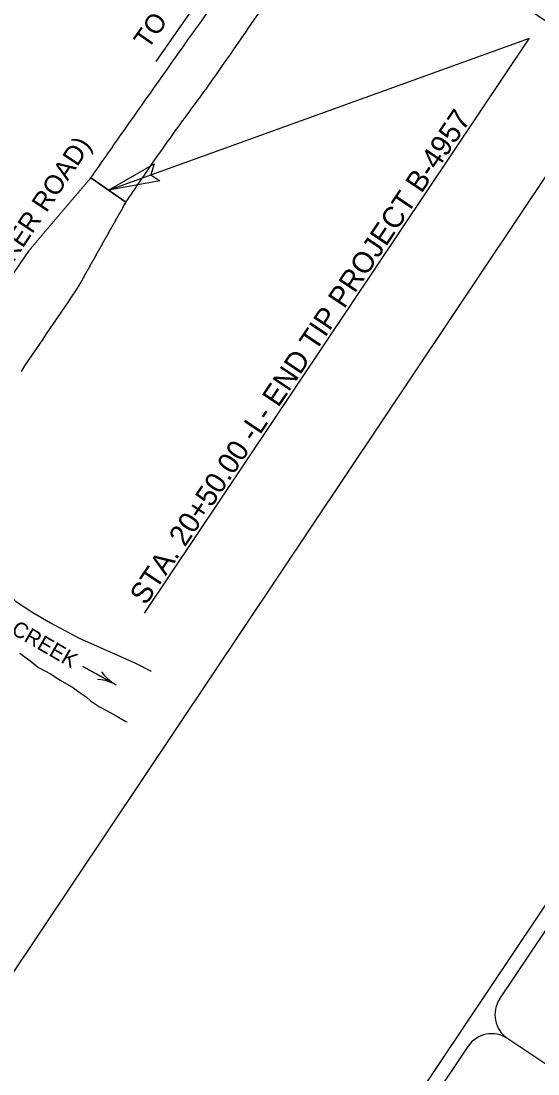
# Model space of a CAD drawing. Extents: x 1715610 to 1720914, y 798298 to 802505.
# Drawn here: x 1717668 to 1717939, y 800836 to 801387 of the extents above; entities that cross this region are included whole.
import ezdxf

# ---------------------------------------------------------------- set-up
doc = ezdxf.new("R2010")
doc.units = 0
for name, color, linetype in [('Default', 7, 'Continuous'), ('Old_Level_3', 7, 'Continuous'), ('Prop DSN Text', 7, 'Continuous'), ('Prop Paved Shoulder', 7, 'Continuous'), ('Prop Shade Medium', 7, 'Continuous'), ('Prop Terminator CELL', 7, 'Continuous'), ('Sheet Title CELL', 7, 'Continuous')]:
    doc.layers.add(name, color=color, linetype=linetype)

# ---------------------------------------------------------------- blocks, each defined once
blk = doc.blocks.new('EXIST HYDRO RIVER FLOW ARROW')
at = {"layer": 'Default'}
blk.add_line((0, 0), (0, 0), dxfattribs=at)
blk.add_lwpolyline([(0, 0.04575), (0.03775, 0.03), (0.07725, 0.01725), (0.118, 0.00775), (0.159, 0.0015), (0.2, 0), (-0.2, 0), (0.2, 0), (0.159, -0.0015), (0.118, -0.00775), (0.07725, -0.01725), (0.03775, -0.03), (0, -0.04575)], dxfattribs=at)

msp = doc.modelspace()

# ---------------------------------------------------------------- linework, layer by layer
at = {"layer": 'Old_Level_3'}
for points in [[(1717605.94, 801111.76), (1717612.79, 801109.04), (1717616.17, 801107.46), (1717622.88, 801104.61), (1717634.87, 801098.17), (1717639.69, 801095.36), (1717644.84, 801093.04), (1717654.93, 801089.79), (1717659.08, 801087.53), (1717662.76, 801085.55), (1717665.17, 801083.21), (1717674.36, 801077.27), (1717683.55, 801072), (1717698.55, 801063.91), (1717727.72, 801050.92)], [(1717667.51, 801055.97), (1717672.17, 801052.48), (1717677.33, 801048.47), (1717683.5, 801045.15), (1717688.67, 801041.86), (1717695.56, 801037.89), (1717698.56, 801035.68), (1717702.27, 801033.19), (1717704.51, 801031.03), (1717709.23, 801027.9), (1717712.43, 801026.24), (1717717.13, 801023.81), (1717723.03, 801020.3), (1717723.71, 801020.05)], [(1717727.61, 801050.97), (1717727.72, 801050.92), (1717736.2, 801046.69)]]:
    msp.add_lwpolyline(points, dxfattribs=at)
for points in [[(1717704.66, 801304.87), (1717720.57, 801327.61), (1717755.53, 801377.08), (1717788.31, 801423.35), (1717810.22, 801454.82)], [(1717723, 801292.11), (1717738.53, 801314.79), (1717747.21, 801327.08), (1717756.08, 801339.25), (1717764.97, 801351.4), (1717773.68, 801363.68), (1717805.81, 801410.44), (1717827.75, 801442.62)]]:
    msp.add_spline(points, degree=3, dxfattribs=at)
at = {"layer": 'Prop DSN Text'}
for p, q in [((1717738.85, 801365.79), (1717793.38, 801444.08)), ((1717713.83, 801298.49), (1717934.3, 801377.96)), ((1717732.84, 801076.97), (1717934.3, 801377.96))]:
    msp.add_line(p, q, dxfattribs=at)
msp.add_lwpolyline([(1717114.49, 800787.07), (1717648.17, 801584.42), (1717980.46, 801362.01), (1717446.79, 800564.66)], close=True, dxfattribs=at)
at = {"layer": 'Prop Paved Shoulder'}
msp.add_line((1717723, 801292.11), (1717704.66, 801304.87), dxfattribs=at)
for radius in [5716, 5684]:
    msp.add_arc((1722391.71, 798042.03), radius, 145.65923, 146.20506, dxfattribs=at)
for points in [[(1717672.02, 801266.5), (1717672.46, 801267.02), (1717672.9, 801267.54), (1717673.34, 801268.06), (1717673.78, 801268.58), (1717674.22, 801269.1), (1717674.66, 801269.62), (1717675.1, 801270.14), (1717675.54, 801270.66), (1717675.98, 801271.18), (1717676.41, 801271.7), (1717676.85, 801272.22), (1717677.29, 801272.74), (1717677.73, 801273.26), (1717678.17, 801273.78), (1717678.61, 801274.3), (1717679.05, 801274.82), (1717679.49, 801275.34), (1717679.93, 801275.86), (1717680.37, 801276.38), (1717680.81, 801276.9), (1717681.25, 801277.42), (1717681.69, 801277.94), (1717682.13, 801278.46), (1717682.57, 801278.98), (1717683.01, 801279.5), (1717683.45, 801280.02), (1717683.9, 801280.54), (1717684.34, 801281.06), (1717684.78, 801281.58), (1717685.22, 801282.1), (1717685.66, 801282.61), (1717686.1, 801283.13), (1717686.54, 801283.65), (1717686.98, 801284.17), (1717687.42, 801284.69), (1717687.86, 801285.21), (1717688.3, 801285.73), (1717688.74, 801286.24), (1717689.19, 801286.76), (1717689.63, 801287.28), (1717690.07, 801287.8), (1717690.51, 801288.32), (1717690.95, 801288.84), (1717691.39, 801289.35), (1717691.83, 801289.87), (1717692.27, 801290.39), (1717692.72, 801290.91), (1717693.16, 801291.43), (1717693.6, 801291.94), (1717694.04, 801292.46), (1717694.48, 801292.98), (1717694.93, 801293.5), (1717695.37, 801294.02), (1717695.81, 801294.53), (1717696.25, 801295.05), (1717696.69, 801295.57), (1717697.14, 801296.09), (1717697.58, 801296.6), (1717698.02, 801297.12), (1717698.46, 801297.64), (1717698.91, 801298.15), (1717699.35, 801298.67), (1717699.79, 801299.19), (1717700.23, 801299.71), (1717700.68, 801300.22), (1717701.12, 801300.74), (1717701.56, 801301.26), (1717702, 801301.77), (1717702.45, 801302.29), (1717702.89, 801302.81), (1717703.33, 801303.32), (1717703.78, 801303.84), (1717704.66, 801304.87)], [(1717698.44, 801248.45), (1717698.77, 801249.04), (1717699.1, 801249.63), (1717699.43, 801250.22), (1717699.76, 801250.81), (1717700.09, 801251.4), (1717700.42, 801252), (1717700.75, 801252.59), (1717701.08, 801253.18), (1717701.41, 801253.77), (1717701.74, 801254.36), (1717702.07, 801254.95), (1717702.4, 801255.54), (1717702.73, 801256.13), (1717703.06, 801256.72), (1717703.39, 801257.31), (1717703.72, 801257.9), (1717704.05, 801258.49), (1717704.38, 801259.09), (1717704.71, 801259.68), (1717705.04, 801260.27), (1717705.37, 801260.86), (1717705.7, 801261.45), (1717706.03, 801262.04), (1717706.36, 801262.63), (1717706.69, 801263.22), (1717707.03, 801263.81), (1717707.36, 801264.4), (1717707.69, 801264.99), (1717708.02, 801265.58), (1717708.35, 801266.17), (1717708.68, 801266.76), (1717709.01, 801267.35), (1717709.34, 801267.94), (1717709.68, 801268.53), (1717710.01, 801269.12), (1717710.34, 801269.71), (1717710.67, 801270.3), (1717711, 801270.89), (1717711.33, 801271.48), (1717711.67, 801272.07), (1717712, 801272.66), (1717712.33, 801273.25), (1717712.66, 801273.84), (1717712.99, 801274.43), (1717713.33, 801275.02), (1717713.66, 801275.61), (1717713.99, 801276.2), (1717714.32, 801276.79), (1717714.66, 801277.38), (1717714.99, 801277.97), (1717715.32, 801278.56), (1717715.66, 801279.15), (1717715.99, 801279.74), (1717716.32, 801280.33), (1717716.65, 801280.92), (1717716.99, 801281.5), (1717717.32, 801282.09), (1717717.65, 801282.68), (1717717.99, 801283.27), (1717718.32, 801283.86), (1717718.65, 801284.45), (1717718.99, 801285.04), (1717719.32, 801285.63), (1717719.66, 801286.22), (1717719.99, 801286.81), (1717720.32, 801287.4), (1717720.66, 801287.99), (1717720.99, 801288.57), (1717721.33, 801289.16), (1717721.66, 801289.75), (1717721.99, 801290.34), (1717722.33, 801290.93), (1717723, 801292.11)]]:
    msp.add_spline(points, degree=3, dxfattribs=at)
at = {"layer": 'Prop Shade Medium'}
msp.add_line((1717704.66, 801304.87), (1717723, 801292.11), dxfattribs=at)
msp.add_line((1717704.66, 801304.87), (1717723, 801292.11), dxfattribs=at)
msp.add_arc((1722391.71, 798042.03), 5684, 145.65923, 146.20506, dxfattribs=at)
msp.add_arc((1722391.71, 798042.03), 5684, 145.65923, 146.20506, dxfattribs=at)
for points in [[(1717672.02, 801266.5), (1717672.46, 801267.02), (1717672.9, 801267.54), (1717673.34, 801268.06), (1717673.78, 801268.58), (1717674.22, 801269.1), (1717674.66, 801269.62), (1717675.1, 801270.14), (1717675.54, 801270.66), (1717675.98, 801271.18), (1717676.41, 801271.7), (1717676.85, 801272.22), (1717677.29, 801272.74), (1717677.73, 801273.26), (1717678.17, 801273.78), (1717678.61, 801274.3), (1717679.05, 801274.82), (1717679.49, 801275.34), (1717679.93, 801275.86), (1717680.37, 801276.38), (1717680.81, 801276.9), (1717681.25, 801277.42), (1717681.69, 801277.94), (1717682.13, 801278.46), (1717682.57, 801278.98), (1717683.01, 801279.5), (1717683.45, 801280.02), (1717683.9, 801280.54), (1717684.34, 801281.06), (1717684.78, 801281.58), (1717685.22, 801282.1), (1717685.66, 801282.61), (1717686.1, 801283.13), (1717686.54, 801283.65), (1717686.98, 801284.17), (1717687.42, 801284.69), (1717687.86, 801285.21), (1717688.3, 801285.73), (1717688.74, 801286.24), (1717689.19, 801286.76), (1717689.63, 801287.28), (1717690.07, 801287.8), (1717690.51, 801288.32), (1717690.95, 801288.84), (1717691.39, 801289.35), (1717691.83, 801289.87), (1717692.27, 801290.39), (1717692.72, 801290.91), (1717693.16, 801291.43), (1717693.6, 801291.94), (1717694.04, 801292.46), (1717694.48, 801292.98), (1717694.93, 801293.5), (1717695.37, 801294.02), (1717695.81, 801294.53), (1717696.25, 801295.05), (1717696.69, 801295.57), (1717697.14, 801296.09), (1717697.58, 801296.6), (1717698.02, 801297.12), (1717698.46, 801297.64), (1717698.91, 801298.15), (1717699.35, 801298.67), (1717699.79, 801299.19), (1717700.23, 801299.71), (1717700.68, 801300.22), (1717701.12, 801300.74), (1717701.56, 801301.26), (1717702, 801301.77), (1717702.45, 801302.29), (1717702.89, 801302.81), (1717703.33, 801303.32), (1717703.78, 801303.84), (1717704.66, 801304.87)], [(1717672.02, 801266.5), (1717672.46, 801267.02), (1717672.9, 801267.54), (1717673.34, 801268.06), (1717673.78, 801268.58), (1717674.22, 801269.1), (1717674.66, 801269.62), (1717675.1, 801270.14), (1717675.54, 801270.66), (1717675.98, 801271.18), (1717676.41, 801271.7), (1717676.85, 801272.22), (1717677.29, 801272.74), (1717677.73, 801273.26), (1717678.17, 801273.78), (1717678.61, 801274.3), (1717679.05, 801274.82), (1717679.49, 801275.34), (1717679.93, 801275.86), (1717680.37, 801276.38), (1717680.81, 801276.9), (1717681.25, 801277.42), (1717681.69, 801277.94), (1717682.13, 801278.46), (1717682.57, 801278.98), (1717683.01, 801279.5), (1717683.45, 801280.02), (1717683.9, 801280.54), (1717684.34, 801281.06), (1717684.78, 801281.58), (1717685.22, 801282.1), (1717685.66, 801282.61), (1717686.1, 801283.13), (1717686.54, 801283.65), (1717686.98, 801284.17), (1717687.42, 801284.69), (1717687.86, 801285.21), (1717688.3, 801285.73), (1717688.74, 801286.24), (1717689.19, 801286.76), (1717689.63, 801287.28), (1717690.07, 801287.8), (1717690.51, 801288.32), (1717690.95, 801288.84), (1717691.39, 801289.35), (1717691.83, 801289.87), (1717692.27, 801290.39), (1717692.72, 801290.91), (1717693.16, 801291.43), (1717693.6, 801291.94), (1717694.04, 801292.46), (1717694.48, 801292.98), (1717694.93, 801293.5), (1717695.37, 801294.02), (1717695.81, 801294.53), (1717696.25, 801295.05), (1717696.69, 801295.57), (1717697.14, 801296.09), (1717697.58, 801296.6), (1717698.02, 801297.12), (1717698.46, 801297.64), (1717698.91, 801298.15), (1717699.35, 801298.67), (1717699.79, 801299.19), (1717700.23, 801299.71), (1717700.68, 801300.22), (1717701.12, 801300.74), (1717701.56, 801301.26), (1717702, 801301.77), (1717702.45, 801302.29), (1717702.89, 801302.81), (1717703.33, 801303.32), (1717703.78, 801303.84), (1717704.66, 801304.87)], [(1717723, 801292.11), (1717722.33, 801290.93), (1717721.99, 801290.34), (1717721.66, 801289.75), (1717721.33, 801289.16), (1717720.99, 801288.57), (1717720.66, 801287.99), (1717720.32, 801287.4), (1717719.99, 801286.81), (1717719.66, 801286.22), (1717719.32, 801285.63), (1717718.99, 801285.04), (1717718.65, 801284.45), (1717718.32, 801283.86), (1717717.99, 801283.27), (1717717.65, 801282.68), (1717717.32, 801282.09), (1717716.99, 801281.5), (1717716.65, 801280.92), (1717716.32, 801280.33), (1717715.99, 801279.74), (1717715.66, 801279.15), (1717715.32, 801278.56), (1717714.99, 801277.97), (1717714.66, 801277.38), (1717714.32, 801276.79), (1717713.99, 801276.2), (1717713.66, 801275.61), (1717713.33, 801275.02), (1717712.99, 801274.43), (1717712.66, 801273.84), (1717712.33, 801273.25), (1717712, 801272.66), (1717711.67, 801272.07), (1717711.33, 801271.48), (1717711, 801270.89), (1717710.67, 801270.3), (1717710.34, 801269.71), (1717710.01, 801269.12), (1717709.68, 801268.53), (1717709.34, 801267.94), (1717709.01, 801267.35), (1717708.68, 801266.76), (1717708.35, 801266.17), (1717708.02, 801265.58), (1717707.69, 801264.99), (1717707.36, 801264.4), (1717707.03, 801263.81), (1717706.69, 801263.22), (1717706.36, 801262.63), (1717706.03, 801262.04), (1717705.7, 801261.45), (1717705.37, 801260.86), (1717705.04, 801260.27), (1717704.71, 801259.68), (1717704.38, 801259.09), (1717704.05, 801258.49), (1717703.72, 801257.9), (1717703.39, 801257.31), (1717703.06, 801256.72), (1717702.73, 801256.13), (1717702.4, 801255.54), (1717702.07, 801254.95), (1717701.74, 801254.36), (1717701.41, 801253.77), (1717701.08, 801253.18), (1717700.75, 801252.59), (1717700.42, 801252), (1717700.09, 801251.4), (1717699.76, 801250.81), (1717699.43, 801250.22), (1717699.1, 801249.63), (1717698.77, 801249.04), (1717698.44, 801248.45)], [(1717723, 801292.11), (1717722.33, 801290.93), (1717721.99, 801290.34), (1717721.66, 801289.75), (1717721.33, 801289.16), (1717720.99, 801288.57), (1717720.66, 801287.99), (1717720.32, 801287.4), (1717719.99, 801286.81), (1717719.66, 801286.22), (1717719.32, 801285.63), (1717718.99, 801285.04), (1717718.65, 801284.45), (1717718.32, 801283.86), (1717717.99, 801283.27), (1717717.65, 801282.68), (1717717.32, 801282.09), (1717716.99, 801281.5), (1717716.65, 801280.92), (1717716.32, 801280.33), (1717715.99, 801279.74), (1717715.66, 801279.15), (1717715.32, 801278.56), (1717714.99, 801277.97), (1717714.66, 801277.38), (1717714.32, 801276.79), (1717713.99, 801276.2), (1717713.66, 801275.61), (1717713.33, 801275.02), (1717712.99, 801274.43), (1717712.66, 801273.84), (1717712.33, 801273.25), (1717712, 801272.66), (1717711.67, 801272.07), (1717711.33, 801271.48), (1717711, 801270.89), (1717710.67, 801270.3), (1717710.34, 801269.71), (1717710.01, 801269.12), (1717709.68, 801268.53), (1717709.34, 801267.94), (1717709.01, 801267.35), (1717708.68, 801266.76), (1717708.35, 801266.17), (1717708.02, 801265.58), (1717707.69, 801264.99), (1717707.36, 801264.4), (1717707.03, 801263.81), (1717706.69, 801263.22), (1717706.36, 801262.63), (1717706.03, 801262.04), (1717705.7, 801261.45), (1717705.37, 801260.86), (1717705.04, 801260.27), (1717704.71, 801259.68), (1717704.38, 801259.09), (1717704.05, 801258.49), (1717703.72, 801257.9), (1717703.39, 801257.31), (1717703.06, 801256.72), (1717702.73, 801256.13), (1717702.4, 801255.54), (1717702.07, 801254.95), (1717701.74, 801254.36), (1717701.41, 801253.77), (1717701.08, 801253.18), (1717700.75, 801252.59), (1717700.42, 801252), (1717700.09, 801251.4), (1717699.76, 801250.81), (1717699.43, 801250.22), (1717699.1, 801249.63), (1717698.77, 801249.04), (1717698.44, 801248.45)]]:
    msp.add_spline(points, degree=3, dxfattribs=at)
at = {"layer": 'Prop Terminator CELL'}
msp.add_lwpolyline([(1717740.81, 801303.27), (1717713.83, 801298.49), (1717737.74, 801312.21), (1717736.13, 801306.53)], close=True, dxfattribs=at)
at = {"layer": 'Sheet Title CELL'}
for p, q in [((1717295.23, 799956.81), (1718479.99, 801726.91)), ((1717918.87, 800875.09), (1718156.66, 801230.35)), ((1717922.99, 800854.28), (1718122.44, 800720.78)), ((1717585.15, 800376.45), (1717902.2, 800850.14))]:
    msp.add_line(p, q, dxfattribs=at)
for centre, start, end in [((1717931.28, 800866.78), 146.2051, 236.2051), ((1717914.6, 800841.85), 56.2051, 146.2051)]:
    msp.add_arc(centre, 15, start, end, dxfattribs=at)

# ---------------------------------------------------------------- block references
at = {"layer": 'Old_Level_3', "xscale": 50, "yscale": 50, "rotation": -28.804336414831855}
msp.add_blockref('EXIST HYDRO RIVER FLOW ARROW', (1717709.16, 801044.31), dxfattribs=at)

# ---------------------------------------------------------------- texts
at = {"layer": 'Prop DSN Text'}
for s, height, rotation, p in [('TO BUS I-85', 10, 55.1408, (1717734.64, 801371.79)), ('STA. 20+50.00 -L- END TIP PROJECT B-4957', 11, 56.2051, (1717733.43, 801080.67)), ('SR 1193 (BAKER ROAD)', 10, 56.2051, (1717620.58, 801195.47)), ('RICHLAND CREEK', 8.1, 329.9329, (1717611.87, 801095.82))]:
    msp.add_text(s, height=height, rotation=rotation, dxfattribs=at).set_placement(p)

doc.saveas('drawing.dxf')
